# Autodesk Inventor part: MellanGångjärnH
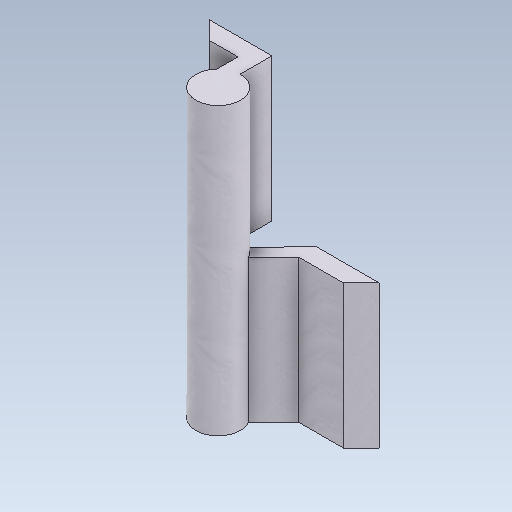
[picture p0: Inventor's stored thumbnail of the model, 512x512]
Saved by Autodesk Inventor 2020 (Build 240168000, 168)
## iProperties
Created: 2019-06
Part Number: MellanGångjärnH
Material: Aluminum 6061, Welded
Document SubType Name: Modeling
Designer: cl
Density: 2.7 g/cm^3
Appearance: Weld - Aluminum
Author: cl
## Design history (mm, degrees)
sketch "Sketch1"
  geometry: L1 (0, 0)-(35, 0); L2 (0, 0)-(10, 10); L3 (10, 10)-(35, 10); L4 (35, 10)-(48.901, 24.182); L5 (35, 0)-(53.9, 19.282); L6 (48.901, 24.182)-(85.631, -11.821); A1 r 12.5 centre (59.801, 30.302) between (53.9, 19.282) and (48.901, 24.182)
  constraints: 12 end point, 2 horizontal, 2 point on circle, 1 centre point, 1 parallel, 1 perpendicular, 1 point on line
  dimensions: "d4" = 35 distance of L1.start L1.end; "d6" = 45 deg angle of L1 L2; "d7" = 10 distance between parallel lines of L1 L3; "d8" = 25 distance of L2.end L3.end; "d9" = 27 distance of L1.end L5.end; "d10" = 7 distance between parallel lines of L5 L4; "d11" = 25 diameter of A1
extrude "Extrusion1" new body sketch "Sketch1" distance "d12" = 80; taper "d13" = 0 deg
sketch "Sketch2"
  geometry: L1 (-48.901, -24.182)-(-35, -10) reference; L2 (-35, -10)-(-10, -10) reference; L3 (-10, -10)-(0, 0) reference; L4 (0, 0)-(-35, 0) reference; L5 (-35, 0)-(-53.9, -19.282) reference; L6 (-60, -17.803)-(-60, 0); L7 (-60, 0)-(-95, 0); L8 (-95, 0)-(-85, -10); L9 (-95, 0)-(-80.858, 0); L10 (-85, -10)-(-69, -10); L11 (-69, -10)-(-69, -21.839); L12 (0, 0)-(-35, 0) reference; A1 r 12.5 centre (-59.801, -30.302) between (-69, -21.839) and (-60, -17.803); A2 r 12.5 centre (-59.801, -30.302) between (-53.9, -19.282) and (-48.901, -24.182) reference; A3 r 12.5 centre (-59.801, -30.302) between (-53.9, -19.282) and (-48.901, -24.182) reference; A4 r 12.5 centre (-59.801, -30.302) between (-53.9, -19.282) and (-48.901, -24.182) reference
  constraints: 12 end point, 3 horizontal, 2 point on circle, 2 vertical, 1 centre point, 1 coincident, 1 collinear, 1 equal length
  dimensions: "d14" = 25 distance of L4.end L6.end; "d15" = 35 distance of L6.end L7.end; "d16" = 45 deg angle of L8 L9; "d17" = 10 distance between parallel lines of L7 L10; "d22" = 25 diameter of A1; "d23" = 9 distance between parallel lines of L11 L6
extrude "Extrusion2" join sketch "Sketch2" distance "d24" = 80; taper "d25" = 0 deg
body "Solid1"
node "Projected Loop1"
node "Projected Loop2"
